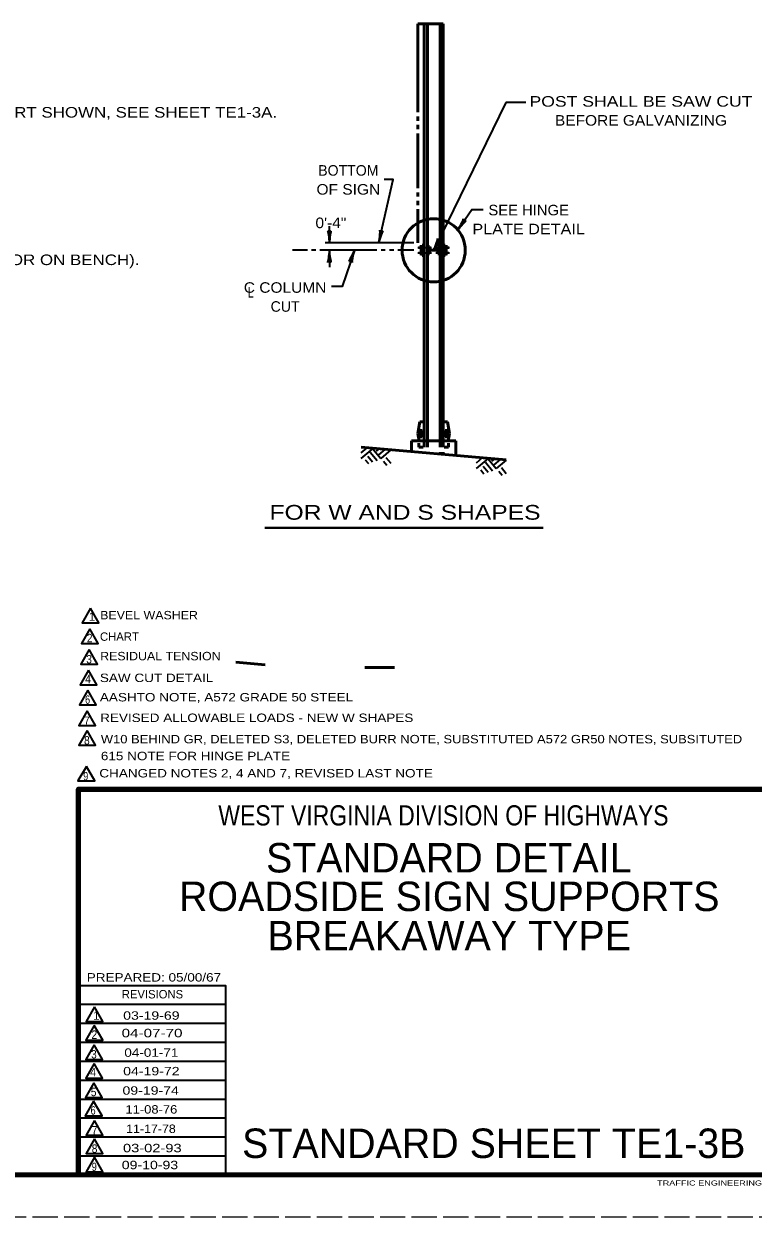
# Model space of a CAD drawing. Extents: x -2 to 835, y 0 to 440.
# Drawn here: x 482.9 to 656.1, y -0.4 to 282.9 of the extents above; entities that cross this region are included whole.
import ezdxf
from ezdxf.enums import TextEntityAlignment as Align

# ---------------------------------------------------------------- set-up
doc = ezdxf.new("R2010")
doc.units = 0
doc.linetypes.add('LONG_DASHED', pattern=[7.5, 6, -1.5])
doc.linetypes.add('SHORT_DASHED', pattern=[2.7, 1.5, -1.2])
doc.layers.add('1', color=7, linetype='Continuous', lineweight=53)
doc.layers.add('61', color=7, linetype='Continuous', lineweight=35)

msp = doc.modelspace()

# ---------------------------------------------------------------- linework, layer by layer
at = {"layer": '1'}
for p, q in [((576.456, 282.859), (582.456, 282.859)), ((576.456, 282.859), (576.456, 261.859)), ((577.956, 282.859), (577.956, 183.859)), ((578.706, 282.859), (578.706, 183.859)), ((581.706, 282.859), (581.706, 183.859)), ((582.456, 282.859), (582.456, 183.859)), ((576.456, 260.859), (576.456, 259.859)), ((576.456, 258.859), (576.456, 257.859)), ((576.456, 256.859), (576.456, 243.859)), ((576.456, 242.859), (576.456, 241.859)), ((576.456, 240.859), (576.456, 239.859)), ((576.456, 238.859), (576.456, 230.859)), ((576.956, 229.984), (577.456, 229.984)), ((576.956, 229.984), (576.956, 229.484)), ((576.956, 229.484), (577.456, 229.484)), ((577.456, 230.359), (577.956, 230.359)), ((577.456, 230.359), (577.456, 227.859)), ((579.206, 229.984), (578.706, 229.984)), ((579.206, 229.484), (578.706, 229.484)), ((579.206, 229.984), (579.206, 229.484)), ((581.706, 229.984), (581.206, 229.984)), ((581.206, 229.984), (581.206, 229.484)), ((581.706, 229.484), (581.206, 229.484)), ((582.456, 230.359), (582.956, 230.359)), ((582.956, 230.359), (582.956, 227.859)), ((582.956, 229.984), (583.456, 229.984)), ((582.956, 229.484), (583.456, 229.484)), ((583.456, 229.984), (583.456, 229.484)), ((576.956, 228.734), (577.456, 228.734)), ((576.956, 228.734), (576.956, 228.234)), ((576.956, 228.234), (577.456, 228.234)), ((577.456, 227.859), (577.956, 227.859)), ((578.706, 229.109), (581.706, 229.109)), ((579.206, 228.734), (578.706, 228.734)), ((579.206, 228.234), (578.706, 228.234)), ((579.206, 228.734), (579.206, 228.234)), ((581.206, 228.734), (581.206, 228.234)), ((581.706, 228.734), (581.206, 228.734)), ((581.706, 228.234), (581.206, 228.234)), ((582.456, 227.859), (582.956, 227.859)), ((582.956, 228.734), (583.456, 228.734)), ((582.956, 228.234), (583.456, 228.234)), ((583.456, 228.734), (583.456, 228.234)), ((576.956, 188.359), (576.456, 185.609)), ((576.956, 188.359), (577.956, 188.359)), ((583.456, 188.359), (582.456, 188.359)), ((583.456, 188.359), (583.956, 185.609)), ((576.456, 185.609), (577.956, 185.609)), ((576.774, 183.859), (576.456, 185.609)), ((576.502, 185.859), (577.956, 185.859)), ((576.502, 185.359), (577.956, 185.359)), ((576.979, 185.859), (576.979, 186.359)), ((576.979, 186.359), (577.479, 186.359)), ((576.979, 184.859), (576.979, 185.359)), ((576.979, 184.859), (577.479, 184.859)), ((577.479, 185.859), (577.479, 186.359)), ((577.479, 184.859), (577.479, 185.359)), ((583.911, 185.859), (582.456, 185.859)), ((583.956, 185.609), (582.456, 185.609)), ((583.911, 185.359), (582.456, 185.359)), ((582.934, 185.859), (582.934, 186.359)), ((582.934, 186.359), (583.434, 186.359)), ((582.934, 184.859), (582.934, 185.359)), ((582.934, 184.859), (583.434, 184.859)), ((583.434, 185.859), (583.434, 186.359)), ((583.434, 184.859), (583.434, 185.359)), ((583.638, 183.859), (583.956, 185.609)), ((563.023, 182.36), (597.392, 179.353)), ((574.956, 183.859), (585.456, 183.859)), ((574.956, 183.859), (574.956, 181.316)), ((576.706, 183.359), (576.706, 182.359)), ((576.706, 182.359), (577.706, 182.359)), ((583.706, 182.359), (582.706, 182.359)), ((583.706, 183.359), (583.706, 182.359)), ((585.456, 183.859), (585.456, 180.397)), ((533.248, 131.325), (540.221, 130.714)), ((563.869, 130.102), (570.869, 130.102))]:
    msp.add_line(p, q, dxfattribs=at)
at = {"layer": '1', "lineweight": 35}
for p, q in [((597.372, 264.205), (580.206, 229.109)), ((602.123, 264.205), (597.372, 264.205)), ((555.456, 230.859), (555.456, 234.859)), ((575.456, 230.859), (554.456, 230.859)), ((576.456, 229.734), (579.706, 229.734)), ((580.706, 229.734), (583.956, 229.734)), ((550.206, 229.109), (546.706, 229.109)), ((552.206, 229.109), (551.206, 229.109)), ((566.706, 229.109), (553.206, 229.109)), ((555.456, 229.109), (555.456, 225.109)), ((568.706, 229.109), (567.706, 229.109)), ((570.706, 229.109), (569.706, 229.109)), ((575.456, 229.109), (571.706, 229.109)), ((576.456, 228.484), (579.706, 228.484)), ((580.706, 228.484), (583.956, 228.484)), ((564.334, 182.205), (562.904, 181.005)), ((565.749, 182.081), (562.911, 179.699)), ((565.649, 182.09), (567.649, 179.706)), ((567.164, 181.957), (566.555, 181.428)), ((568.598, 181.832), (567.103, 180.577)), ((570.013, 181.708), (567.649, 179.706)), ((563.967, 179.386), (564.751, 178.474)), ((564.546, 180.259), (565.709, 178.872)), ((565.087, 181.175), (566.78, 179.18)), ((568.276, 179.069), (569.058, 178.138)), ((568.874, 179.94), (570.038, 178.554)), ((591.73, 179.808), (590.3, 178.608)), ((593.144, 179.684), (590.306, 177.302)), ((592.483, 178.778), (594.175, 176.783)), ((593.045, 179.693), (595.045, 177.31)), ((594.559, 179.56), (593.951, 179.031)), ((595.993, 179.435), (594.498, 178.18)), ((597.408, 179.311), (595.045, 177.31)), ((591.363, 176.989), (592.146, 176.077)), ((591.941, 177.862), (593.105, 176.475)), ((595.671, 176.672), (596.453, 175.741)), ((596.27, 177.544), (597.433, 176.157)), ((530.873, 50.029), (495.893, 50.029)), ((530.873, 45.529), (495.893, 45.529)), ((530.873, 41.029), (495.893, 41.029)), ((530.873, 36.509), (495.893, 36.509)), ((530.873, 32.029), (495.893, 32.029)), ((530.873, 27.549), (495.893, 27.549)), ((530.873, 23.049), (495.893, 23.049)), ((530.873, 18.549), (495.893, 18.549)), ((530.873, 14.029), (495.893, 14.029))]:
    msp.add_line(p, q, dxfattribs=at)
at = {"layer": '1', "linetype": 'SHORT_DASHED'}
for p, q in [((577.956, 183.859), (577.956, 181.053)), ((578.706, 183.859), (578.706, 180.987)), ((581.706, 183.859), (581.706, 180.725)), ((582.456, 183.859), (582.456, 180.659))]:
    msp.add_line(p, q, dxfattribs=at)
at = {"layer": '1', "lineweight": 40}
msp.add_line((540.139, 163.228), (606.163, 163.228), dxfattribs=at)
at = {"layer": '1', "lineweight": 35}
for points in [[(567.179, 230.989), (570.59, 245.901), (568.443, 245.901)], [(585.945, 233.938), (589.288, 238.824), (591.941, 238.824)], [(561.368, 229.093), (558.462, 220.5), (555.936, 220.5)], [(530.873, 9.549), (530.873, 54.509), (495.893, 54.509)]]:
    msp.add_lwpolyline(points, dxfattribs=at)
for points in [[(498.72, 144.149), (496.72, 140.685), (500.72, 140.685)], [(498.562, 139.236), (496.562, 135.772), (500.562, 135.772)], [(498.403, 134.324), (496.403, 130.86), (500.403, 130.86)], [(498.245, 129.411), (496.245, 125.947), (500.245, 125.947)], [(498.086, 124.657), (496.086, 121.193), (500.086, 121.193)], [(497.928, 119.766), (495.928, 116.302), (499.928, 116.302)], [(497.928, 115.116), (495.928, 111.652), (499.928, 111.652)], [(497.732, 106.603), (495.732, 103.139), (499.732, 103.139)], [(499.685, 49.522), (497.685, 46.058), (501.685, 46.058)], [(499.629, 45.096), (497.629, 41.632), (501.629, 41.632)], [(499.574, 40.504), (497.574, 37.04), (501.574, 37.04)], [(499.574, 36.023), (497.574, 32.559), (501.574, 32.559)], [(499.519, 31.486), (497.519, 28.022), (501.519, 28.022)], [(499.463, 27.116), (497.463, 23.651), (501.463, 23.651)], [(499.685, 22.524), (497.685, 19.059), (501.685, 19.059)], [(499.685, 18.141), (497.685, 14.677), (501.685, 14.677)], [(499.685, 13.816), (497.685, 10.352), (501.685, 10.352)]]:
    msp.add_lwpolyline(points, close=True, dxfattribs=at)
at = {"layer": '1', "lineweight": 158}
msp.add_lwpolyline([(495.873, 9.589), (495.873, 101.169), (667.533, 101.169)], dxfattribs=at)
at = {"layer": '1'}
msp.add_circle((580.206, 229.109), 7.5, dxfattribs=at)
at = {"layer": '1', "lineweight": 40}
for centre, major_axis, ratio, start_param, end_param in [((586.333, 234.994), (-0.879, -1.562), 0.122415, 0.8963533, 3.1415927), ((586.333, 234.994), (-0.879, -1.562), 0.122415, 0.8963533, 3.1415927), ((586.753, 234.743), (1.137, 1.351), 0.07063, 6.2823074, 8.5597026), ((586.753, 234.743), (1.137, 1.351), 0.07063, 6.2823074, 8.5597026), ((555.18, 231.951), (0.156, -1.786), 0.122415, 0.8963533, 3.1415927), ((555.18, 231.951), (0.156, -1.786), 0.122415, 0.8963533, 3.1415927), ((555.668, 231.98), (-0.176, -1.756), 0.07063, 3.1407148, 5.41811), ((555.668, 231.98), (-0.176, -1.756), 0.07063, 3.1407148, 5.41811), ((567.153, 232.114), (-0.246, -1.776), 0.122415, 0.8963533, 3.1415927), ((567.635, 232.034), (0.563, 1.673), 0.07063, 6.2823074, 8.5597026), ((580.437, 230.211), (-0.644, -1.673), 0.122415, 0.8963533, 3.1415927), ((580.889, 230.023), (0.93, 1.501), 0.07063, 6.2823074, 8.5597026), ((555.245, 227.989), (0.176, 1.756), 0.07063, 3.1407148, 5.41811), ((555.733, 228.018), (-0.156, 1.786), 0.122415, 0.8963533, 3.1415927), ((560.809, 228.1), (-0.729, -1.608), 0.07063, 6.2823074, 8.5597026), ((561.28, 227.971), (0.424, 1.742), 0.122415, 0.8963533, 3.1415927)]:
    msp.add_ellipse(centre, major_axis=major_axis, ratio=ratio, start_param=start_param, end_param=end_param, dxfattribs=at)
at = {"layer": '61', "lineweight": 158}
msp.add_line((667.533, 9.589), (28.473, 9.609), dxfattribs=at)
at = {"layer": '61', "linetype": 'LONG_DASHED', "lineweight": 13}
msp.add_line((678.473, -0.391), (-1.587, -0.411), dxfattribs=at)

# ---------------------------------------------------------------- texts
at = {"layer": '1'}
for s, height, width, p in [('POST SHALL BE SAW CUT', 2.5, 1.25, (629.424, 263.202)), ('BEFORE GALVANIZING', 2.5, 1.1, (629.424, 258.702)), ('OF SIGN', 2.5, 1.1, (559.943, 242.321)), ('SEE HINGE', 2.5, 1.05, (602.751, 237.404)), ('0\'-4"', 2.5, 1.1, (555.797, 234.37)), ('PLATE DETAIL', 2.5, 1.15, (602.751, 232.904)), ('C COLUMN', 2.5, 1.1, (544.927, 219.02)), ('L', 2.5, 0.75, (536.746, 217.891)), ('FOR W AND S SHAPES', 3.5, 1.25, (573.405, 165.151)), ('WEST VIRGINIA DIVISION OF HIGHWAYS', 4.795, 0.85, (582.521, 92.569)), ('03-19-69', 2, 1.25, (513.173, 46.449)), ('04-07-70', 2, 1.35, (513.34, 42.288)), ('04-01-71', 2, 1.2, (513.173, 37.649)), ('04-19-72', 2, 1.25, (513.173, 33.249)), ('09-19-74', 2, 1.25, (513.013, 28.649)), ('11-08-76', 2, 1.15, (513.173, 24.169)), ('11-17-78', 2, 1.1, (513.073, 19.569)), ('03-02-93', 2, 1.3, (513.396, 14.989)), ('09-10-93', 2, 1.25, (512.842, 10.969))]:
    msp.add_text(s, height=height, dxfattribs=dict(at, width=width)).set_placement(p, align=Align.CENTER)
for s, height, width, p in [('FOR BASE CONNECTIONS TO BE USED IN CONJUNCTION WITH THE POLE SELECTION CHART SHOWN, SEE SHEET TE1-3A.', 2.5, 1.2, (302.967, 260.611)), ('CAN BE USED IF THE SUPPORTS ARE LOCATED BEHIND GUARDRAIL (OR ON BENCH).', 2.5, 1.2, (342.723, 225.602)), ('BEVEL WASHER', 2, 1.1, (501.015, 141.498)), ('2', 2, 0.9, (497.856, 136.056)), ('RESIDUAL TENSION', 2, 1.1, (501.015, 131.772)), ('3', 2, 0.9, (497.715, 131.035)), ('4', 2, 0.95, (497.435, 126.33)), ('SAW CUT DETAIL', 2, 1.2, (500.945, 126.611)), ('6', 2, 0.8, (497.435, 121.45)), ('AASHTO NOTE, A572 GRADE 50 STEEL', 2, 1.2, (500.945, 122.012)), ('REVISED ALLOWABLE LOADS - NEW W SHAPES', 2, 1.2, (501.015, 117.132)), ('7', 2, 0.9, (497.189, 116.429)), ('8', 2, 0.9, (497.189, 111.779)), ('W10 BEHIND GR, DELETED S3, DELETED BURR NOTE, SUBSTITUTED A572 GR50 NOTES, SUBSITUTED', 2, 1.15, (501.178, 112.062)), ('615 NOTE FOR HINGE PLATE', 2, 1.2, (501.178, 108.062)), ('9', 2, 0.8, (496.993, 103.266)), ('CHANGED NOTES 2, 4 AND 7, REVISED LAST NOTE', 2, 1.2, (500.818, 103.968)), ('PREPARED: 05/00/67', 1.998, 1.2, (497.833, 55.509)), ('2', 2, 0.9, (498.966, 41.909)), ('3', 2, 0.9, (498.855, 37.261)), ('4', 2, 0.95, (498.634, 33.001)), ('5', 2, 0.9, (498.8, 28.299)), ('6', 2, 0.8, (498.744, 23.928)), ('7', 2, 0.9, (499.021, 19.225)), ('8', 2, 0.9, (499.021, 14.843)), ('9', 2, 0.8, (499.021, 10.518)), ('TRAFFIC ENGINEERING DIVISION', 1.2, 1.35, (633.253, 7.089))]:
    msp.add_text(s, height=height, dxfattribs=dict(at, width=width)).set_placement(p)
for s, height, p in [('BOTTOM', 2.5, (559.943, 246.821)), ('CUT', 2.5, (544.927, 214.52)), ('STANDARD DETAIL', 6.993, (583.79, 81.409)), ('ROADSIDE SIGN SUPPORTS', 6.993, (583.899, 72.249)), ('BREAKAWAY TYPE', 6.993, (583.899, 62.933))]:
    msp.add_text(s, height=height, dxfattribs=at).set_placement(p, align=Align.CENTER)
for s, height, p in [('1', 2, (498.347, 141.146)), ('CHART', 2, (500.98, 136.407)), ('REVISIONS', 1.998, (506.153, 51.509)), ('1', 2, (499.353, 46.445)), ('STANDARD SHEET TE1-3B', 6.993, (534.713, 13.629))]:
    msp.add_text(s, height=height, dxfattribs=at).set_placement(p)

doc.saveas('drawing.dxf')
